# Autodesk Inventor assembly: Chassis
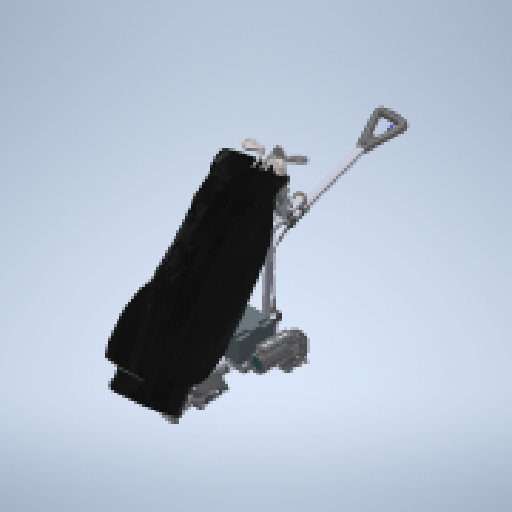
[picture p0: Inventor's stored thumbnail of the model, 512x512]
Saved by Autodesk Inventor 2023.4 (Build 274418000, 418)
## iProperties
Created: 2011-01
Part Number: Chassis
Document SubType Name: Assembly
Designer: eric
Mass: 5424.55 g
Surface Area: 15292.6 cm^2
Volume: 5424.55 cm^3
Density: 1 g/cm^3
Author: eric
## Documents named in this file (33)
- C:\Users\bruno\Documents\1-Cours-2024-25\TSsI\7-Dynamique\chariot de golf\chariot_de_golf\chariot_de_golf_trolem\Chassis.iam
- C:\Users\bruno\Documents\1-Cours-2024-25\TSsI\7-Dynamique\chariot de golf\chariot_de_golf\chariot_de_golf_trolem\59batterie_Defaut.ipt
- C:\Users\bruno\Documents\1-Cours-2024-25\TSsI\7-Dynamique\chariot de golf\chariot_de_golf\chariot_de_golf_trolem\montage1chassis_Defaut.iam
- C:\Users\bruno\Documents\1-Cours-2024-25\TSsI\7-Dynamique\chariot de golf\chariot_de_golf\chariot_de_golf_trolem\40Enjoliveur_M8_Defaut.ipt
- C:\Users\bruno\Documents\1-Cours-2024-25\TSsI\7-Dynamique\chariot de golf\chariot_de_golf\chariot_de_golf_trolem\5.1Vis CBLX M8-55.ipt
- C:\Users\bruno\Documents\1-Cours-2024-25\TSsI\7-Dynamique\chariot de golf\chariot_de_golf\chariot_de_golf_trolem\5.1cache-ecrouM10_Defaut.ipt
- C:\Users\bruno\Documents\1-Cours-2024-25\TSsI\7-Dynamique\chariot de golf\chariot_de_golf\chariot_de_golf_trolem\montage2timon_Defaut.iam
- C:\Users\bruno\Documents\1-Cours-2024-25\TSsI\7-Dynamique\chariot de golf\chariot_de_golf\chariot_de_golf_trolem\montage4tube_alu_Defaut.iam
- C:\Users\bruno\Documents\1-Cours-2024-25\TSsI\7-Dynamique\chariot de golf\chariot_de_golf\chariot_de_golf_trolem\montage_6cable_Defaut.iam
- C:\Users\bruno\Documents\1-Cours-2024-25\TSsI\7-Dynamique\chariot de golf\chariot_de_golf\chariot_de_golf_trolem\44Rondelle_M8_Defaut.ipt
- C:\Users\bruno\Documents\1-Cours-2024-25\TSsI\7-Dynamique\chariot de golf\chariot_de_golf\chariot_de_golf_trolem\33vis M6_60.ipt
- C:\Users\bruno\Documents\1-Cours-2024-25\TSsI\7-Dynamique\chariot de golf\chariot_de_golf\chariot_de_golf_trolem\32vis M8_60.ipt
- C:\Users\bruno\Documents\1-Cours-2024-25\TSsI\7-Dynamique\chariot de golf\chariot_de_golf\chariot_de_golf_trolem\39Ecrou H_ FR_ M8.ipt
- C:\Users\bruno\Documents\1-Cours-2024-25\TSsI\7-Dynamique\chariot de golf\chariot_de_golf\chariot_de_golf_trolem\35Vis_CBLZ_M6_55.ipt
- C:\Users\bruno\Documents\1-Cours-2024-25\TSsI\7-Dynamique\chariot de golf\chariot_de_golf\chariot_de_golf_trolem\36Ecrou H_ FR_ M6.ipt
- C:\Users\bruno\Documents\1-Cours-2024-25\TSsI\7-Dynamique\chariot de golf\chariot_de_golf\chariot_de_golf_trolem\30Ressort_e1.5_Defaut.ipt
- C:\Users\bruno\Documents\1-Cours-2024-25\TSsI\7-Dynamique\chariot de golf\chariot_de_golf\chariot_de_golf_trolem\5.1 ressort_Defaut.ipt
- C:\Users\bruno\Documents\1-Cours-2024-25\TSsI\7-Dynamique\chariot de golf\chariot_de_golf\chariot_de_golf_trolem\5.1Vis CBLX M8-45.ipt
- C:\Users\bruno\Documents\1-Cours-2024-25\TSsI\7-Dynamique\chariot de golf\chariot_de_golf\chariot_de_golf_trolem\39Ecrou H_FR_ M8.ipt
- C:\Users\bruno\Documents\1-Cours-2024-25\TSsI\7-Dynamique\chariot de golf\chariot_de_golf\chariot_de_golf_trolem\5.1rondelle plastique e8,5x2_Defaut.ipt
- C:\Users\bruno\Documents\1-Cours-2024-25\TSsI\7-Dynamique\chariot de golf\chariot_de_golf\chariot_de_golf_trolem\5.1carre_monte_Defaut.iam
- C:\Users\bruno\Documents\1-Cours-2024-25\TSsI\7-Dynamique\chariot de golf\chariot_de_golf\chariot_de_golf_trolem\70Rondelle_M10_Defaut.ipt
- C:\Users\bruno\Documents\1-Cours-2024-25\TSsI\7-Dynamique\chariot de golf\chariot_de_golf\chariot_de_golf_trolem\5.1Ecrou freine M 10.ipt
- C:\Users\bruno\Documents\1-Cours-2024-25\TSsI\7-Dynamique\chariot de golf\chariot_de_golf\chariot_de_golf_trolem\5.1Rondelle_e8_Defaut.ipt
- C:\Users\bruno\Documents\1-Cours-2024-25\TSsI\7-Dynamique\chariot de golf\chariot_de_golf\chariot_de_golf_trolem\68protection_roues_Defaut.ipt
- C:\Users\bruno\Documents\1-Cours-2024-25\TSsI\7-Dynamique\chariot de golf\chariot_de_golf\chariot_de_golf_trolem\38Rondelle plate_M8.ipt
- C:\Users\bruno\Documents\1-Cours-2024-25\TSsI\7-Dynamique\chariot de golf\chariot_de_golf\chariot_de_golf_trolem\69VisHM8_100_Defaut.ipt
- C:\Users\bruno\Documents\1-Cours-2024-25\TSsI\7-Dynamique\chariot de golf\chariot_de_golf\chariot_de_golf_trolem\12motoreducteur_Defaut.iam
- C:\Users\bruno\Documents\1-Cours-2024-25\TSsI\7-Dynamique\chariot de golf\chariot_de_golf\chariot_de_golf_trolem\5.1support_roue_monte_Defaut.iam
- C:\Users\bruno\Documents\1-Cours-2024-25\TSsI\7-Dynamique\chariot de golf\chariot_de_golf\chariot_de_golf_trolem\sac.ipt
- C:\Users\bruno\Documents\1-Cours-2024-25\TSsI\7-Dynamique\chariot de golf\chariot_de_golf\chariot_de_golf_trolem\Sac-golf\Golfbag_4.ipt
- C:\Users\bruno\Documents\1-Cours-2024-25\TSsI\7-Dynamique\chariot de golf\chariot_de_golf\chariot_de_golf_trolem\Sac-golf\Club5.ipt
- C:\Users\bruno\Documents\1-Cours-2024-25\TSsI\7-Dynamique\chariot de golf\chariot_de_golf\chariot_de_golf_trolem\Sac-golf\Club7.ipt
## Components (55 placed, 32 different names)
1. 5.1support_roue_monte_Defaut:1 [sub-assembly]
2. 12motoreducteur_Defaut:1 [sub-assembly]
3. 35Vis_CBLZ_M6_55:2
4. 35Vis_CBLZ_M6_55:4
5. 35Vis_CBLZ_M6_55:3
6. 36Ecrou H_ FR_ M6:3
7. 36Ecrou H_ FR_ M6:4
8. 36Ecrou H_ FR_ M6:5
9. 36Ecrou H_ FR_ M6:2
10. 70Rondelle_M10_Defaut:3
11. 70Rondelle_M10_Defaut:4
12. 70Rondelle_M10_Defaut:5
13. 70Rondelle_M10_Defaut:2
14. 38Rondelle plate_M8:4
15. 38Rondelle plate_M8:5
16. 69VisHM8_100_Defaut:1
17. 38Rondelle plate_M8:1
18. 38Rondelle plate_M8:2
19. 38Rondelle plate_M8:3
20. 39Ecrou H_ FR_ M8:3
21. 68protection_roues_Defaut:1
22. 39Ecrou H_ FR_ M8:2
23. 5.1Rondelle_e8_Defaut:1
24. 5.1rondelle plastique e8,5x2_Defaut:3
25. 5.1Ecrou freine M 10:1
26. 70Rondelle_M10_Defaut:1
27. 5.1carre_monte_Defaut:1 [sub-assembly]
28. 5.1rondelle plastique e8,5x2_Defaut:1
29. 5.1rondelle plastique e8,5x2_Defaut:2
30. 39Ecrou H_FR_ M8:1
31. 5.1Vis CBLX M8-45:1
32. 5.1 ressort_Defaut:1
33. 35Vis_CBLZ_M6_55:1
34. 44Rondelle_M8_Defaut:2
35. 30Ressort_e1.5_Defaut:1
36. 33vis M6_60:1
37. 32vis M8_60:1
38. 44Rondelle_M8_Defaut:1
39. 39Ecrou H_ FR_ M8:1
40. 36Ecrou H_ FR_ M6:1
41. montage2timon_Defaut:1 [sub-assembly]
42. montage_6cable_Defaut:1 [sub-assembly]
43. montage4tube_alu_Defaut:1 [sub-assembly]
44. 5.1Vis CBLX M8-55:1
45. 5.1cache-ecrouM10_Defaut:1
46. 40Enjoliveur_M8_Defaut:1
47. montage1chassis_Defaut:1 [sub-assembly]
48. 59batterie_Defaut:1
49. sac:1
50. Golfbag_4:1 — Placage:1, Placage:2
51. Club5:1 — Placage:1, Placage:3, Placage:5
52. Club7:1 — Placage:2, Placage:4
53. Club7:2 — Placage:5
54. Club5:2 — Placage:3
55. Club5:3 — Placage:4
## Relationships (5: Mate 5)
- Placage:1 [Mate]: Golfbag_4:1 ↔ Club5:1
- Placage:2 [Mate]: Golfbag_4:1 ↔ Club7:1
- Placage:3 [Mate]: Club5:1 ↔ Club5:2
- Placage:4 [Mate]: Club7:1 ↔ Club5:3
- Placage:5 [Mate]: Club5:1 ↔ Club7:2
